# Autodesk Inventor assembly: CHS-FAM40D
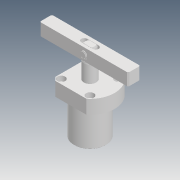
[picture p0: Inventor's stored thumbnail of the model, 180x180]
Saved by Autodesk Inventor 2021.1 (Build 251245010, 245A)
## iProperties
Created: 2019-04
Part Number: CHS-FAM40D
Description: STEP AP203
Document SubType Name: Assembly
Designer: user
Title: chs-fam40d_asm.STEP
Revision Number: ÈÎºÎ
Sending System: SolidWorks 2017
Preprocessor: SwSTEP 2.0
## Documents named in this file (6)
- D:\Vault_2016\Projekty\Clamptek\Hydraulic\CHS\CHS-40\Inventor\CHS-FAM40D\CHS-FAM40D.iam
- D:\Vault_2016\Projekty\Clamptek\Hydraulic\CHS\CHS-40\Inventor\CHS-FAM40D\CHS-FAM40-03.ipt
- D:\Vault_2016\Projekty\Clamptek\Hydraulic\CHS\CHS-40\Inventor\CHS-FAM40D\CHS-40D-02_2.ipt
- D:\Vault_2016\Projekty\Clamptek\Hydraulic\CHS\CHS-40\Inventor\CHS-FAM40D\CHS-40D-01_3.ipt
- D:\Vault_2016\Projekty\Clamptek\Hydraulic\CHS\CHS-40\Inventor\CHS-FAM40D\XIAO.ipt
- D:\Vault_2016\Projekty\Clamptek\Hydraulic\CHS\CHS-40\Inventor\CHS-FAM40D\12ÖáÓÃµ²È¦.ipt
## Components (6 placed, 6 different names)
1. CHS-FAM40-03_1
2. CHS-40D-02_2_2
3. CHS-40D-01_3_3
4. XIAO_4
5. 12ÖáÓÃµ²È¦_5
6. 12ÖáÓÃµ²È¦_6
